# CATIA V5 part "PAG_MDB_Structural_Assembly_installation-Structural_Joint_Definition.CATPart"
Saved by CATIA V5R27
Part number: PAG_MDB_Structural_Assembly_installation-Structural_Joints_Definition
Bounding box of the stored display mesh (mm): x -105 to 305, y -98.579 to 108.038, z -6.5 to 44.5
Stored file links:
  H:\STEP-Test-cases\public\installation-with-fasteners\tc4-assembly-PAG\PAG_MDB_Structural_Assembly_installation-Structural_Joint_Definition.CATPart
  H:\STEP-Test-cases\public\installation-with-fasteners\tc4-assembly\PAG_MDB_Structural_Assembly_instalation.CATProduct
  H:\STEP-Test-cases\public\installation-with-fasteners\tc4-assembly-PAG\frame.CATPart
  H:\STEP-Test-cases\public\installation-with-fasteners\tc4-assembly-PAG\PAG_MDB_Structural_Assembly_installation.CATProduct
  H:\STEP-Test-cases\public\installation-with-fasteners\tc4-assembly-PAG\V5PIRANHA.CATPart
  H:\STEP-Test-cases\public\installation-with-fasteners\tc4-assembly-PAG\panel.CATPart
  H:\STEP-Test-cases\public\installation-with-fasteners\tc4-assembly-PAG\Fasteners.CATPart
  H:\STEP-Test-cases\public\installation-with-fasteners\tc4-assembly-PAG\PIRANHA.CATPart
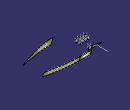
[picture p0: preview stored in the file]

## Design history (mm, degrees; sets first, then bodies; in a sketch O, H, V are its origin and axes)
AxisSystem1: origin (0, 0, 0), X (1, 0, 0), Y (0, 1, 0), Z (0, 0, 1)
Assembly_Annotation_Set_11 "CATTPSSet"
TTRSSet1
Set1
  DatumSurface1 to DatumSurface7: linked copy from another document
Set2 "MatingDefinition_1"
  Set3 "fasteners"
    UdfFeature1 "en6115v4": UdfInputSpec1 {project ToProject {point type Coord, X -65 {= UdfFeature1.Xe}, Y -24 {= UdfFeature1.Ye}, Z 10 {= UdfFeature1.Ze}}, Support DatumSurface1}, UdfInputSpec2 {linenormal RefPoint {project ToProject {point type Coord, X -65 {= UdfFeature1.Xe}, Y -24 {= UdfFeature1.Ye}, Z 10 {= UdfFeature1.Ze}}, Support DatumSurface1}, RefSkin DatumSurface1, Start 0, End 16.5}, References_Item_Stack "en6115V4-10;;;asna2531-4", Fastener_Type "Lockbolt Hi-Lite", Fastener_Diameter 6.4, Head_Orientation 90, Geometrical_Length 16.5, Hole_Depth 15.5, Xe -65, Ye -24, Ze 10
    UdfFeature2 "en6115v4": UdfInputSpec1 {project ToProject {point type Coord, X -85 {= UdfFeature2.Xe}, Y -24 {= UdfFeature2.Ye}, Z 10 {= UdfFeature2.Ze}}, Support DatumSurface1}, UdfInputSpec2 {linenormal RefPoint {project ToProject {point type Coord, X -85 {= UdfFeature2.Xe}, Y -24 {= UdfFeature2.Ye}, Z 10 {= UdfFeature2.Ze}}, Support DatumSurface1}, RefSkin DatumSurface1, Start 0, End 16.5}, References_Item_Stack "en6115V4-10;;;asna2531-4", Fastener_Type "Lockbolt Hi-Lite", Fastener_Diameter 6.4, Head_Orientation 90, Geometrical_Length 16.5, Hole_Depth 15.5, Xe -85, Ye -24, Ze 10
    UdfFeature3 "en6115v4": UdfInputSpec1 {project ToProject {point type Coord, X -45 {= UdfFeature3.Xe}, Y -24 {= UdfFeature3.Ye}, Z 10 {= UdfFeature3.Ze}}, Support DatumSurface1}, UdfInputSpec2 {linenormal RefPoint {project ToProject {point type Coord, X -45 {= UdfFeature3.Xe}, Y -24 {= UdfFeature3.Ye}, Z 10 {= UdfFeature3.Ze}}, Support DatumSurface1}, RefSkin DatumSurface1, Start 0, End 16.5}, References_Item_Stack "en6115V4-10;;;asna2531-4", Fastener_Type "Lockbolt Hi-Lite", Fastener_Diameter 6.4, Head_Orientation 90, Geometrical_Length 16.5, Hole_Depth 15.5, Xe -45, Ye -24, Ze 10
    UdfFeature4 "en6115v4": UdfInputSpec1 {project ToProject {point type Coord, X -25 {= UdfFeature4.Xe}, Y -24 {= UdfFeature4.Ye}, Z 10 {= UdfFeature4.Ze}}, Support DatumSurface1}, UdfInputSpec2 {linenormal RefPoint {project ToProject {point type Coord, X -25 {= UdfFeature4.Xe}, Y -24 {= UdfFeature4.Ye}, Z 10 {= UdfFeature4.Ze}}, Support DatumSurface1}, RefSkin DatumSurface1, Start 0, End 16.5}, References_Item_Stack "en6115V4-10;;;asna2531-4", Fastener_Type "Lockbolt Hi-Lite", Fastener_Diameter 6.4, Head_Orientation 90, Geometrical_Length 16.5, Hole_Depth 15.5, Xe -25, Ye -24, Ze 10
    UdfFeature5 "en6115v4": UdfInputSpec1 {project ToProject {point type Coord, X -65 {= UdfFeature5.Xe}, Y 0 {= UdfFeature5.Ye}, Z 10 {= UdfFeature5.Ze}}, Support DatumSurface1}, UdfInputSpec2 {linenormal RefPoint {project ToProject {point type Coord, X -65 {= UdfFeature5.Xe}, Y 0 {= UdfFeature5.Ye}, Z 10 {= UdfFeature5.Ze}}, Support DatumSurface1}, RefSkin DatumSurface1, Start 0, End 16.5}, References_Item_Stack "en6115V4-10;;;asna2531-4", Fastener_Type "Lockbolt Hi-Lite", Fastener_Diameter 6.4, Head_Orientation 90, Geometrical_Length 16.5, Hole_Depth 15.5, Xe -65, Ye 0, Ze 10
    UdfFeature6 "en6115v4": UdfInputSpec1 {project ToProject {point type Coord, X -85 {= UdfFeature6.Xe}, Y 0 {= UdfFeature6.Ye}, Z 10 {= UdfFeature6.Ze}}, Support DatumSurface1}, UdfInputSpec2 {linenormal RefPoint {project ToProject {point type Coord, X -85 {= UdfFeature6.Xe}, Y 0 {= UdfFeature6.Ye}, Z 10 {= UdfFeature6.Ze}}, Support DatumSurface1}, RefSkin DatumSurface1, Start 0, End 16.5}, References_Item_Stack "en6115V4-10;;;asna2531-4", Fastener_Type "Lockbolt Hi-Lite", Fastener_Diameter 6.4, Head_Orientation 90, Geometrical_Length 16.5, Hole_Depth 15.5, Xe -85, Ye 0, Ze 10
    UdfFeature7 "en6115v4": UdfInputSpec1 {project ToProject {point type Coord, X -45 {= UdfFeature7.Xe}, Y 0 {= UdfFeature7.Ye}, Z 10 {= UdfFeature7.Ze}}, Support DatumSurface1}, UdfInputSpec2 {linenormal RefPoint {project ToProject {point type Coord, X -45 {= UdfFeature7.Xe}, Y 0 {= UdfFeature7.Ye}, Z 10 {= UdfFeature7.Ze}}, Support DatumSurface1}, RefSkin DatumSurface1, Start 0, End 16.5}, References_Item_Stack "en6115V4-10;;;asna2531-4", Fastener_Type "Lockbolt Hi-Lite", Fastener_Diameter 6.4, Head_Orientation 90, Geometrical_Length 16.5, Hole_Depth 15.5, Xe -45, Ye 0, Ze 10
    UdfFeature8 "en6115v4": UdfInputSpec1 {project ToProject {point type Coord, X -25 {= UdfFeature8.Xe}, Y 0 {= UdfFeature8.Ye}, Z 10 {= UdfFeature8.Ze}}, Support DatumSurface1}, UdfInputSpec2 {linenormal RefPoint {project ToProject {point type Coord, X -25 {= UdfFeature8.Xe}, Y 0 {= UdfFeature8.Ye}, Z 10 {= UdfFeature8.Ze}}, Support DatumSurface1}, RefSkin DatumSurface1, Start 0, End 16.5}, References_Item_Stack "en6115V4-10;;;asna2531-4", Fastener_Type "Lockbolt Hi-Lite", Fastener_Diameter 6.4, Head_Orientation 90, Geometrical_Length 16.5, Hole_Depth 15.5, Xe -25, Ye 0, Ze 10
    UdfFeature9 "en6115v4": UdfInputSpec1 {project ToProject {point type Coord, X -25 {= UdfFeature9.Xe}, Y 66 {= UdfFeature9.Ye}, Z 20 {= UdfFeature9.Ze}}, Support DatumSurface2}, UdfInputSpec2 {linenormal RefPoint {project ToProject {point type Coord, X -25 {= UdfFeature9.Xe}, Y 66 {= UdfFeature9.Ye}, Z 20 {= UdfFeature9.Ze}}, Support DatumSurface2}, RefSkin DatumSurface2, Start 0, End 16.5}, References_Item_Stack "en6115V4-10;;;asna2531-4", Fastener_Type "Lockbolt Hi-Lite", Fastener_Diameter 6.4, Head_Orientation 90, Geometrical_Length 16.5, Hole_Depth 15.5, Xe -25, Ye 66, Ze 20
Set4 "Mating_Definition_2"
  Set5 "fasteners"
    UdfFeature10 "en6101ad3": UdfInputSpec1 {project ToProject {point type Coord, X 169.787 {= UdfFeature10.Xe}, Y -90.556 {= UdfFeature10.Ye}, Z 10.688 {= UdfFeature10.Ze}}, Support DatumSurface4}, UdfInputSpec2 {linenormal RefPoint {project ToProject {point type Coord, X 169.787 {= UdfFeature10.Xe}, Y -90.556 {= UdfFeature10.Ye}, Z 10.688 {= UdfFeature10.Ze}}, Support DatumSurface4}, RefSkin DatumSurface4, Start 0, End 6.2 {= UdfFeature10.Hole_Depth}}, References_Item_Stack "en6101AD3", Fastener_Type "Rivet", Fastener_Diameter 2.4, Head_Orientation 0, Geometrical_Length 6.3, Xe 169.787, Ye -90.556, Ze 10.688, Hole_Depth 6.2, Countersunk_depth 1, Countersunk_angle 100
    UdfFeature11 "en6101ad3": UdfInputSpec1 {project ToProject {point type Coord, X 149.858 {= UdfFeature11.Xe}, Y -92.463 {= UdfFeature11.Ye}, Z 11.189 {= UdfFeature11.Ze}}, Support DatumSurface4}, UdfInputSpec2 {linenormal RefPoint {project ToProject {point type Coord, X 149.858 {= UdfFeature11.Xe}, Y -92.463 {= UdfFeature11.Ye}, Z 11.189 {= UdfFeature11.Ze}}, Support DatumSurface4}, RefSkin DatumSurface4, Start 0, End 6.2 {= UdfFeature11.Hole_Depth}}, References_Item_Stack "en6101AD3", Fastener_Type "Rivet", Fastener_Diameter 2.4, Head_Orientation 0, Geometrical_Length 6.3, Xe 149.858, Ye -92.463, Ze 11.189, Hole_Depth 6.2, Countersunk_depth 1, Countersunk_angle 100
    UdfFeature12 "en6101ad3": UdfInputSpec1 {project ToProject {point type Coord, X 129.915 {= UdfFeature12.Xe}, Y -94.002 {= UdfFeature12.Ye}, Z 11.593 {= UdfFeature12.Ze}}, Support DatumSurface4}, UdfInputSpec2 {linenormal RefPoint {project ToProject {point type Coord, X 129.915 {= UdfFeature12.Xe}, Y -94.002 {= UdfFeature12.Ye}, Z 11.593 {= UdfFeature12.Ze}}, Support DatumSurface4}, RefSkin DatumSurface4, Start 0, End 6.2 {= UdfFeature12.Hole_Depth}}, References_Item_Stack "en6101AD3", Fastener_Type "Rivet", Fastener_Diameter 2.4, Head_Orientation 0, Geometrical_Length 6.3, Xe 129.915, Ye -94.002, Ze 11.593, Hole_Depth 6.2, Countersunk_depth 1, Countersunk_angle 100
    UdfFeature13 "en6101ad3": UdfInputSpec1 {project ToProject {point type Coord, X 109.986 {= UdfFeature13.Xe}, Y -95.175 {= UdfFeature13.Ye}, Z 11.901 {= UdfFeature13.Ze}}, Support DatumSurface4}, UdfInputSpec2 {linenormal RefPoint {project ToProject {point type Coord, X 109.986 {= UdfFeature13.Xe}, Y -95.175 {= UdfFeature13.Ye}, Z 11.901 {= UdfFeature13.Ze}}, Support DatumSurface4}, RefSkin DatumSurface4, Start 0, End 6.2 {= UdfFeature13.Hole_Depth}}, References_Item_Stack "en6101AD3", Fastener_Type "Rivet", Fastener_Diameter 2.4, Head_Orientation 0, Geometrical_Length 6.3, Xe 109.986, Ye -95.175, Ze 11.901, Hole_Depth 6.2, Countersunk_depth 1, Countersunk_angle 100
    UdfFeature14 "en6101ad3": UdfInputSpec1 {project ToProject {point type Coord, X 269.162 {= UdfFeature14.Xe}, Y 82.899 {= UdfFeature14.Ye}, Z 14.936 {= UdfFeature14.Ze}}, Support DatumSurface5}, UdfInputSpec2 {linenormal RefPoint {project ToProject {point type Coord, X 269.162 {= UdfFeature14.Xe}, Y 82.899 {= UdfFeature14.Ye}, Z 14.936 {= UdfFeature14.Ze}}, Support DatumSurface5}, RefSkin DatumSurface5, Start 0, End 6.2 {= UdfFeature14.Hole_Depth}}, References_Item_Stack "en6101AD3", Fastener_Type "Rivet", Fastener_Diameter 2.4, Head_Orientation 0, Geometrical_Length 6.3, Xe 269.162, Ye 82.899, Ze 14.936, Hole_Depth 6.2, Countersunk_depth 1, Countersunk_angle 100
    UdfFeature15 "en6101ad3": UdfInputSpec1 {project ToProject {point type Coord, X 249.318 {= UdfFeature15.Xe}, Y 86.742 {= UdfFeature15.Ye}, Z 13.906 {= UdfFeature15.Ze}}, Support DatumSurface5}, UdfInputSpec2 {linenormal RefPoint {project ToProject {point type Coord, X 249.318 {= UdfFeature15.Xe}, Y 86.742 {= UdfFeature15.Ye}, Z 13.906 {= UdfFeature15.Ze}}, Support DatumSurface5}, RefSkin DatumSurface5, Start 0, End 6.2 {= UdfFeature15.Hole_Depth}}, References_Item_Stack "en6101AD3", Fastener_Type "Rivet", Fastener_Diameter 2.4, Head_Orientation 0, Geometrical_Length 6.3, Xe 249.318, Ye 86.742, Ze 13.906, Hole_Depth 6.2, Countersunk_depth 1, Countersunk_angle 100
    UdfFeature16 "en6101ad3": UdfInputSpec1 {project ToProject {point type Coord, X 229.437 {= UdfFeature16.Xe}, Y 90.203 {= UdfFeature16.Ye}, Z 12.979 {= UdfFeature16.Ze}}, Support DatumSurface5}, UdfInputSpec2 {linenormal RefPoint {project ToProject {point type Coord, X 229.437 {= UdfFeature16.Xe}, Y 90.203 {= UdfFeature16.Ye}, Z 12.979 {= UdfFeature16.Ze}}, Support DatumSurface5}, RefSkin DatumSurface5, Start 0, End 6.2 {= UdfFeature16.Hole_Depth}}, References_Item_Stack "en6101AD3", Fastener_Type "Rivet", Fastener_Diameter 2.4, Head_Orientation 0, Geometrical_Length 6.3, Xe 229.437, Ye 90.203, Ze 12.979, Hole_Depth 6.2, Countersunk_depth 1, Countersunk_angle 100
    UdfFeature17 "en6101ad3": UdfInputSpec1 {project ToProject {point type Coord, X 210.194 {= UdfFeature17.Xe}, Y 93.4 {= UdfFeature17.Ye}, Z 12.927 {= UdfFeature17.Ze}}, Support DatumSurface5}, UdfInputSpec2 {linenormal RefPoint {project ToProject {point type Coord, X 210.194 {= UdfFeature17.Xe}, Y 93.4 {= UdfFeature17.Ye}, Z 12.927 {= UdfFeature17.Ze}}, Support DatumSurface5}, RefSkin DatumSurface5, Start 0, End 6.2 {= UdfFeature17.Hole_Depth}}, References_Item_Stack "en6101AD3", Fastener_Type "Rivet", Fastener_Diameter 2.4, Head_Orientation 0, Geometrical_Length 6.3, Xe 210.194, Ye 93.4, Ze 12.927, Hole_Depth 6.2, Countersunk_depth 1, Countersunk_angle 100
    UdfFeature18 "en6101ad3": UdfInputSpec1 {project ToProject {point type Coord, X 189.659 {= UdfFeature18.Xe}, Y 96.377 {= UdfFeature18.Ye}, Z 12.927 {= UdfFeature18.Ze}}, Support DatumSurface5}, UdfInputSpec2 {linenormal RefPoint {project ToProject {point type Coord, X 189.659 {= UdfFeature18.Xe}, Y 96.377 {= UdfFeature18.Ye}, Z 12.927 {= UdfFeature18.Ze}}, Support DatumSurface5}, RefSkin DatumSurface5, Start 0, End 6.2 {= UdfFeature18.Hole_Depth}}, References_Item_Stack "en6101AD3", Fastener_Type "Rivet", Fastener_Diameter 2.4, Head_Orientation 0, Geometrical_Length 6.3, Xe 189.659, Ye 96.377, Ze 12.927, Hole_Depth 6.2, Countersunk_depth 1, Countersunk_angle 100
    UdfFeature19 "en6101ad3": UdfInputSpec1 {project ToProject {point type Coord, X 169.759 {= UdfFeature19.Xe}, Y 98.861 {= UdfFeature19.Ye}, Z 12.927 {= UdfFeature19.Ze}}, Support DatumSurface5}, UdfInputSpec2 {linenormal RefPoint {project ToProject {point type Coord, X 169.759 {= UdfFeature19.Xe}, Y 98.861 {= UdfFeature19.Ye}, Z 12.927 {= UdfFeature19.Ze}}, Support DatumSurface5}, RefSkin DatumSurface5, Start 0, End 6.2 {= UdfFeature19.Hole_Depth}}, References_Item_Stack "en6101AD3", Fastener_Type "Rivet", Fastener_Diameter 2.4, Head_Orientation 0, Geometrical_Length 6.3, Xe 169.759, Ye 98.861, Ze 12.927, Hole_Depth 6.2, Countersunk_depth 1, Countersunk_angle 100
    UdfFeature20 "en6101ad3": UdfInputSpec1 {project ToProject {point type Coord, X 149.808 {= UdfFeature20.Xe}, Y 100.946 {= UdfFeature20.Ye}, Z 12.927 {= UdfFeature20.Ze}}, Support DatumSurface5}, UdfInputSpec2 {linenormal RefPoint {project ToProject {point type Coord, X 149.808 {= UdfFeature20.Xe}, Y 100.946 {= UdfFeature20.Ye}, Z 12.927 {= UdfFeature20.Ze}}, Support DatumSurface5}, RefSkin DatumSurface5, Start 0, End 6.2 {= UdfFeature20.Hole_Depth}}, References_Item_Stack "en6101AD3", Fastener_Type "Rivet", Fastener_Diameter 2.4, Head_Orientation 0, Geometrical_Length 6.3, Xe 149.808, Ye 100.946, Ze 12.927, Hole_Depth 6.2, Countersunk_depth 1, Countersunk_angle 100
    UdfFeature21 "en6101ad3": UdfInputSpec1 {project ToProject {point type Coord, X 129.294 {= UdfFeature21.Xe}, Y 102.671 {= UdfFeature21.Ye}, Z 12.927 {= UdfFeature21.Ze}}, Support DatumSurface5}, UdfInputSpec2 {linenormal RefPoint {project ToProject {point type Coord, X 129.294 {= UdfFeature21.Xe}, Y 102.671 {= UdfFeature21.Ye}, Z 12.927 {= UdfFeature21.Ze}}, Support DatumSurface5}, RefSkin DatumSurface5, Start 0, End 6.2 {= UdfFeature21.Hole_Depth}}, References_Item_Stack "en6101AD3", Fastener_Type "Rivet", Fastener_Diameter 2.4, Head_Orientation 0, Geometrical_Length 6.3, Xe 129.294, Ye 102.671, Ze 12.927, Hole_Depth 6.2, Countersunk_depth 1, Countersunk_angle 100
    UdfFeature22 "en6101ad3": UdfInputSpec1 {project ToProject {point type Coord, X 109.698 {= UdfFeature22.Xe}, Y 103.293 {= UdfFeature22.Ye}, Z 12.927 {= UdfFeature22.Ze}}, Support DatumSurface5}, UdfInputSpec2 {linenormal RefPoint {project ToProject {point type Coord, X 109.698 {= UdfFeature22.Xe}, Y 103.293 {= UdfFeature22.Ye}, Z 12.927 {= UdfFeature22.Ze}}, Support DatumSurface5}, RefSkin DatumSurface5, Start 0, End 6.2 {= UdfFeature22.Hole_Depth}}, References_Item_Stack "en6101AD3", Fastener_Type "Rivet", Fastener_Diameter 2.4, Head_Orientation 0, Geometrical_Length 6.3, Xe 109.698, Ye 103.293, Ze 12.927, Hole_Depth 6.2, Countersunk_depth 1, Countersunk_angle 100
    UdfFeature23 "en6101ad3": UdfInputSpec1 {project ToProject {point type Coord, X 53.218 {= UdfFeature23.Xe}, Y 105.863 {= UdfFeature23.Ye}, Z 12.925 {= UdfFeature23.Ze}}, Support DatumSurface3}, UdfInputSpec2 {linenormal RefPoint {project ToProject {point type Coord, X 53.218 {= UdfFeature23.Xe}, Y 105.863 {= UdfFeature23.Ye}, Z 12.925 {= UdfFeature23.Ze}}, Support DatumSurface3}, RefSkin DatumSurface3, Start 0, End 6.2 {= UdfFeature23.Hole_Depth}}, References_Item_Stack "en6101AD3", Fastener_Type "Rivet", Fastener_Diameter 2.4, Head_Orientation 0, Geometrical_Length 6.3, Xe 53.218, Ye 105.863, Ze 12.925, Hole_Depth 6.2, Countersunk_depth 1, Countersunk_angle 100
    UdfFeature24 "en6101ad3": UdfInputSpec1 {project ToProject {point type Coord, X 43.222 {= UdfFeature24.Xe}, Y 105.863 {= UdfFeature24.Ye}, Z 12.925 {= UdfFeature24.Ze}}, Support DatumSurface3}, UdfInputSpec2 {linenormal RefPoint {project ToProject {point type Coord, X 43.222 {= UdfFeature24.Xe}, Y 105.863 {= UdfFeature24.Ye}, Z 12.925 {= UdfFeature24.Ze}}, Support DatumSurface3}, RefSkin DatumSurface3, Start 0, End 6.2 {= UdfFeature24.Hole_Depth}}, References_Item_Stack "en6101AD3", Fastener_Type "Rivet", Fastener_Diameter 2.4, Head_Orientation 0, Geometrical_Length 6.3, Xe 43.222, Ye 105.863, Ze 12.925, Hole_Depth 6.2, Countersunk_depth 1, Countersunk_angle 100
    UdfFeature25 "en6101ad3": UdfInputSpec1 {project ToProject {point type Coord, X 33.226 {= UdfFeature25.Xe}, Y 106.058 {= UdfFeature25.Ye}, Z 12.873 {= UdfFeature25.Ze}}, Support DatumSurface3}, UdfInputSpec2 {linenormal RefPoint {project ToProject {point type Coord, X 33.226 {= UdfFeature25.Xe}, Y 106.058 {= UdfFeature25.Ye}, Z 12.873 {= UdfFeature25.Ze}}, Support DatumSurface3}, RefSkin DatumSurface3, Start 0, End 6.2 {= UdfFeature25.Hole_Depth}}, References_Item_Stack "en6101AD3", Fastener_Type "Rivet", Fastener_Diameter 2.4, Head_Orientation 0, Geometrical_Length 6.3, Xe 33.226, Ye 106.058, Ze 12.873, Hole_Depth 6.2, Countersunk_depth 1, Countersunk_angle 100
    UdfFeature26 "en6101ad3": UdfInputSpec1 {project ToProject {point type Coord, X 23.23 {= UdfFeature26.Xe}, Y 106.253 {= UdfFeature26.Ye}, Z 12.821 {= UdfFeature26.Ze}}, Support DatumSurface3}, UdfInputSpec2 {linenormal RefPoint {project ToProject {point type Coord, X 23.23 {= UdfFeature26.Xe}, Y 106.253 {= UdfFeature26.Ye}, Z 12.821 {= UdfFeature26.Ze}}, Support DatumSurface3}, RefSkin DatumSurface3, Start 0, End 6.2 {= UdfFeature26.Hole_Depth}}, References_Item_Stack "en6101AD3", Fastener_Type "Rivet", Fastener_Diameter 2.4, Head_Orientation 0, Geometrical_Length 6.3, Xe 23.23, Ye 106.253, Ze 12.821, Hole_Depth 6.2, Countersunk_depth 1, Countersunk_angle 100
  Set6 "AssemblyShapeJoint_1"
    DatumSurface8 to DatumSurface10
Body1 (main body)
  Solid1: linked copy from another document
Body2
